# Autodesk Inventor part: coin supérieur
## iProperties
Shininess: 64.0
Length Units: 11269
Angle Units: 11279
Time Units: 11290
Mass Units: 11283
Length Display Precision: 3
Angle Display Precision: 2
Compacted: True
Part Number: coin supérieur
Document SubType Name: Modeling
Created: 2005-01
Material: Par défaut
Designer: LEGERET Philippe
Density: 0.0
Volumn: 0.0
Area: 0.0
PropertySet Name: Model Information
Control State: 0
Master: False
Checked Out: False
Author: LEGERET Philippe
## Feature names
1. Extrusion1
2. Perçage1 [Hole]
3. Perçage2 [Hole]
